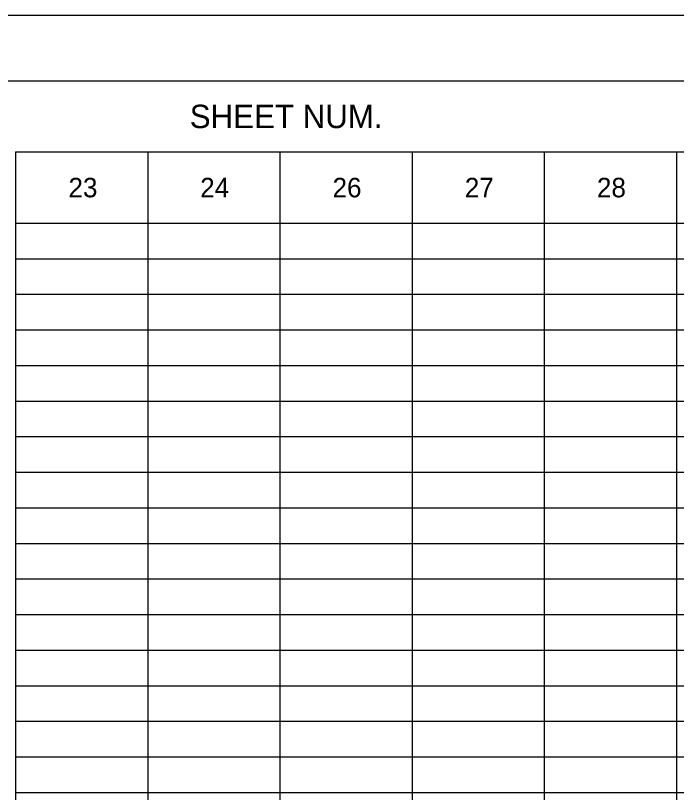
# Model space of a CAD drawing. Extents: x 0 to 34, y 0 to 22.
# Drawn here: x 4.54 to 9.6, y 16.05 to 22 of the extents above; entities that cross this region are included whole.
import ezdxf

# ---------------------------------------------------------------- set-up
doc = ezdxf.new("R2010")
doc.units = 0
for name, color, linetype in [('Default', 7, 'Continuous'), ('SH_Border', 7, 'Continuous'), ('SH_Cut_Line', 7, 'Continuous')]:
    doc.layers.add(name, color=color, linetype=linetype)

msp = doc.modelspace()

# ---------------------------------------------------------------- linework, layer by layer
at = {"layer": 'Default'}
for p, q in [((4.5368, 21.5), (5.549, 21.5)), ((5.549, 21.5), (6.5613, 21.5)), ((6.5613, 21.5), (7.5736, 21.5)), ((7.5736, 21.5), (8.5858, 21.5)), ((8.5858, 21.5), (9.5981, 21.5)), ((9.5981, 21.5), (11.6226, 21.5)), ((4.5368, 20.9549), (5.549, 20.9549)), ((4.5368, 20.9549), (4.5368, 20.6824)), ((5.549, 20.9549), (6.5613, 20.9549)), ((5.549, 20.9549), (5.549, 20.6824)), ((6.5613, 20.9549), (7.5736, 20.9549)), ((6.5613, 20.9549), (6.5613, 20.6824)), ((7.5736, 20.9549), (8.5858, 20.9549)), ((7.5736, 20.9549), (7.5736, 20.6824)), ((8.5858, 20.9549), (9.5981, 20.9549)), ((8.5858, 20.9549), (8.5858, 20.6824)), ((9.5981, 20.9549), (11.6226, 20.9549)), ((9.5981, 20.9549), (9.5981, 20.6824)), ((4.5368, 20.6824), (4.5368, 20.4099)), ((5.549, 20.6824), (5.549, 20.4099)), ((6.5613, 20.6824), (6.5613, 20.4099)), ((7.5736, 20.6824), (7.5736, 20.4099)), ((8.5858, 20.6824), (8.5858, 20.4099)), ((9.5981, 20.6824), (9.5981, 20.4099)), ((4.5368, 20.4099), (5.549, 20.4099)), ((4.5368, 20.4099), (4.5368, 20.1373)), ((5.549, 20.4099), (6.5613, 20.4099)), ((5.549, 20.4099), (5.549, 20.1373)), ((6.5613, 20.4099), (7.5736, 20.4099)), ((6.5613, 20.4099), (6.5613, 20.1373)), ((7.5736, 20.4099), (8.5858, 20.4099)), ((7.5736, 20.4099), (7.5736, 20.1373)), ((8.5858, 20.4099), (9.5981, 20.4099)), ((8.5858, 20.4099), (8.5858, 20.1373)), ((9.5981, 20.4099), (11.6226, 20.4099)), ((9.5981, 20.4099), (9.5981, 20.1373)), ((4.5368, 20.1373), (5.549, 20.1373)), ((4.5368, 20.1373), (4.5368, 18.7747)), ((5.549, 20.1373), (6.5613, 20.1373)), ((5.549, 20.1373), (5.549, 18.7747)), ((6.5613, 20.1373), (7.5736, 20.1373)), ((6.5613, 20.1373), (6.5613, 18.7747)), ((7.5736, 20.1373), (8.5858, 20.1373)), ((7.5736, 20.1373), (7.5736, 18.7747)), ((8.5858, 20.1373), (9.5981, 20.1373)), ((8.5858, 20.1373), (8.5858, 18.7747)), ((9.5981, 20.1373), (11.6226, 20.1373)), ((9.5981, 20.1373), (9.5981, 18.7747)), ((4.5368, 19.8648), (5.549, 19.8648)), ((5.549, 19.8648), (6.5613, 19.8648)), ((6.5613, 19.8648), (7.5736, 19.8648)), ((7.5736, 19.8648), (8.5858, 19.8648)), ((8.5858, 19.8648), (9.5981, 19.8648)), ((9.5981, 19.8648), (11.6226, 19.8648)), ((4.5368, 19.5923), (5.549, 19.5923)), ((5.549, 19.5923), (6.5613, 19.5923)), ((6.5613, 19.5923), (7.5736, 19.5923)), ((7.5736, 19.5923), (8.5858, 19.5923)), ((8.5858, 19.5923), (9.5981, 19.5923)), ((9.5981, 19.5923), (11.6226, 19.5923)), ((4.5368, 19.3197), (5.549, 19.3197)), ((5.549, 19.3197), (6.5613, 19.3197)), ((6.5613, 19.3197), (7.5736, 19.3197)), ((7.5736, 19.3197), (8.5858, 19.3197)), ((8.5858, 19.3197), (9.5981, 19.3197)), ((9.5981, 19.3197), (11.6226, 19.3197)), ((4.5368, 19.0472), (5.549, 19.0472)), ((5.549, 19.0472), (6.5613, 19.0472)), ((6.5613, 19.0472), (7.5736, 19.0472)), ((7.5736, 19.0472), (8.5858, 19.0472)), ((8.5858, 19.0472), (9.5981, 19.0472)), ((9.5981, 19.0472), (11.6226, 19.0472)), ((4.5368, 18.7747), (5.549, 18.7747)), ((4.5368, 18.7747), (4.5368, 18.2296)), ((5.549, 18.7747), (6.5613, 18.7747)), ((5.549, 18.7747), (5.549, 18.2296)), ((6.5613, 18.7747), (7.5736, 18.7747)), ((6.5613, 18.7747), (6.5613, 18.2296)), ((7.5736, 18.7747), (8.5858, 18.7747)), ((7.5736, 18.7747), (7.5736, 18.2296)), ((8.5858, 18.7747), (9.5981, 18.7747)), ((8.5858, 18.7747), (8.5858, 18.2296)), ((9.5981, 18.7747), (11.6226, 18.7747)), ((9.5981, 18.7747), (9.5981, 18.2296)), ((4.5368, 18.5022), (5.549, 18.5022)), ((5.549, 18.5022), (6.5613, 18.5022)), ((6.5613, 18.5022), (7.5736, 18.5022)), ((7.5736, 18.5022), (8.5858, 18.5022)), ((8.5858, 18.5022), (9.5981, 18.5022)), ((9.5981, 18.5022), (11.6226, 18.5022)), ((4.5368, 18.2296), (5.549, 18.2296)), ((4.5368, 18.2296), (4.5368, 17.9571)), ((5.549, 18.2296), (6.5613, 18.2296)), ((5.549, 18.2296), (5.549, 17.9571)), ((6.5613, 18.2296), (7.5736, 18.2296)), ((6.5613, 18.2296), (6.5613, 17.9571)), ((7.5736, 18.2296), (8.5858, 18.2296)), ((7.5736, 18.2296), (7.5736, 17.9571)), ((8.5858, 18.2296), (9.5981, 18.2296)), ((8.5858, 18.2296), (8.5858, 17.9571)), ((9.5981, 18.2296), (11.6226, 18.2296)), ((9.5981, 18.2296), (9.5981, 17.9571)), ((4.5368, 17.9571), (5.549, 17.9571)), ((4.5368, 17.9571), (4.5368, 17.6846)), ((5.549, 17.9571), (6.5613, 17.9571)), ((5.549, 17.9571), (5.549, 17.6846)), ((6.5613, 17.9571), (7.5736, 17.9571)), ((6.5613, 17.9571), (6.5613, 17.6846)), ((7.5736, 17.9571), (8.5858, 17.9571)), ((7.5736, 17.9571), (7.5736, 17.6846)), ((8.5858, 17.9571), (9.5981, 17.9571)), ((8.5858, 17.9571), (8.5858, 17.6846)), ((9.5981, 17.9571), (11.6226, 17.9571)), ((9.5981, 17.9571), (9.5981, 17.6846)), ((4.5368, 17.6846), (5.549, 17.6846)), ((4.5368, 17.6846), (4.5368, 17.412)), ((5.549, 17.6846), (6.5613, 17.6846)), ((5.549, 17.6846), (5.549, 17.412)), ((6.5613, 17.6846), (7.5736, 17.6846)), ((6.5613, 17.6846), (6.5613, 17.412)), ((7.5736, 17.6846), (8.5858, 17.6846)), ((7.5736, 17.6846), (7.5736, 17.412)), ((8.5858, 17.6846), (9.5981, 17.6846)), ((8.5858, 17.6846), (8.5858, 17.412)), ((9.5981, 17.6846), (11.6226, 17.6846)), ((9.5981, 17.6846), (9.5981, 17.412)), ((4.5368, 17.412), (5.549, 17.412)), ((4.5368, 17.412), (4.5368, 17.1395)), ((5.549, 17.412), (6.5613, 17.412)), ((5.549, 17.412), (5.549, 17.1395)), ((6.5613, 17.412), (7.5736, 17.412)), ((6.5613, 17.412), (6.5613, 17.1395)), ((7.5736, 17.412), (8.5858, 17.412)), ((7.5736, 17.412), (7.5736, 17.1395)), ((8.5858, 17.412), (9.5981, 17.412)), ((8.5858, 17.412), (8.5858, 17.1395)), ((9.5981, 17.412), (11.6226, 17.412)), ((9.5981, 17.412), (9.5981, 17.1395)), ((4.5368, 17.1395), (5.549, 17.1395)), ((4.5368, 17.1395), (4.5368, 16.867)), ((5.549, 17.1395), (6.5613, 17.1395)), ((5.549, 17.1395), (5.549, 16.867)), ((6.5613, 17.1395), (7.5736, 17.1395)), ((6.5613, 17.1395), (6.5613, 16.867)), ((7.5736, 17.1395), (8.5858, 17.1395)), ((7.5736, 17.1395), (7.5736, 16.867)), ((8.5858, 17.1395), (9.5981, 17.1395)), ((8.5858, 17.1395), (8.5858, 16.867)), ((9.5981, 17.1395), (11.6226, 17.1395)), ((9.5981, 17.1395), (9.5981, 16.867)), ((4.5368, 16.867), (5.549, 16.867)), ((4.5368, 16.867), (4.5368, 16.3219)), ((5.549, 16.867), (6.5613, 16.867)), ((5.549, 16.867), (5.549, 16.3219)), ((6.5613, 16.867), (7.5736, 16.867)), ((6.5613, 16.867), (6.5613, 16.3219)), ((7.5736, 16.867), (8.5858, 16.867)), ((7.5736, 16.867), (7.5736, 16.3219)), ((8.5858, 16.867), (9.5981, 16.867)), ((8.5858, 16.867), (8.5858, 16.3219)), ((9.5981, 16.867), (11.6226, 16.867)), ((9.5981, 16.867), (9.5981, 16.3219)), ((4.5368, 16.5944), (5.549, 16.5944)), ((5.549, 16.5944), (6.5613, 16.5944)), ((6.5613, 16.5944), (7.5736, 16.5944)), ((7.5736, 16.5944), (8.5858, 16.5944)), ((8.5858, 16.5944), (9.5981, 16.5944)), ((9.5981, 16.5944), (11.6226, 16.5944)), ((4.5368, 16.3219), (5.549, 16.3219)), ((4.5368, 16.3219), (4.5368, 16.0494)), ((5.549, 16.3219), (6.5613, 16.3219)), ((5.549, 16.3219), (5.549, 16.0494)), ((6.5613, 16.3219), (7.5736, 16.3219)), ((6.5613, 16.3219), (6.5613, 16.0494)), ((7.5736, 16.3219), (8.5858, 16.3219)), ((7.5736, 16.3219), (7.5736, 16.0494)), ((8.5858, 16.3219), (9.5981, 16.3219)), ((8.5858, 16.3219), (8.5858, 16.0494)), ((9.5981, 16.3219), (11.6226, 16.3219)), ((9.5981, 16.3219), (9.5981, 16.0494)), ((4.5368, 16.0494), (5.549, 16.0494)), ((4.5368, 16.0494), (4.5368, 15.7768)), ((5.549, 16.0494), (6.5613, 16.0494)), ((5.549, 16.0494), (5.549, 15.7768)), ((6.5613, 16.0494), (7.5736, 16.0494)), ((6.5613, 16.0494), (6.5613, 15.7768)), ((7.5736, 16.0494), (8.5858, 16.0494)), ((7.5736, 16.0494), (7.5736, 15.7768)), ((8.5858, 16.0494), (9.5981, 16.0494)), ((8.5858, 16.0494), (8.5858, 15.7768)), ((9.5981, 16.0494), (11.6226, 16.0494)), ((9.5981, 16.0494), (9.5981, 15.7768))]:
    msp.add_line(p, q, dxfattribs=at)
at = {"layer": 'SH_Border'}
msp.add_lwpolyline([(1.5, 21.5), (33.5, 21.5), (33.5, 0.5), (1.5, 0.5)], close=True, dxfattribs=at)
at = {"layer": 'SH_Cut_Line'}
msp.add_lwpolyline([(0, 0), (34, 0), (34, 22), (0, 22)], close=True, dxfattribs=at)

# ---------------------------------------------------------------- texts
at = {"layer": 'Default'}
for s, height, p in [('SHEET NUM.', 0.17909, (5.8708, 21.1379)), ('23', 0.14924, (4.9421, 20.6078)), ('24', 0.14924, (5.951, 20.6078)), ('26', 0.14924, (6.9644, 20.6078)), ('27', 0.14924, (7.9773, 20.6078)), ('28', 0.14924, (8.9891, 20.6078))]:
    msp.add_text(s, height=height, dxfattribs=at).set_placement(p)

doc.saveas('drawing.dxf')
